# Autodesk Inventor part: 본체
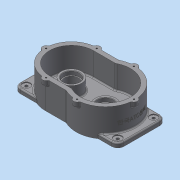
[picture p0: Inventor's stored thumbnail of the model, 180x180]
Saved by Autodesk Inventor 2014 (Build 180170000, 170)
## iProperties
Created: 2025-09
Part Number: 본체
Material: 일반
Document SubType Name: Modeling
Designer: dg
Density: 1 g/cm^3
Appearance: 기본값
Mass: 583.834 g
Surface Area: 1298.21 cm^2
Volume: 583.834 cm^3
Author: dg
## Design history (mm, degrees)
sketch "스케치1"
  geometry: L1 (-118.5, -55)-(118.5, -55); L2 (118.5, -55)-(118.5, 55); L3 (118.5, 55)-(-118.5, 55); L4 (-118.5, 55)-(-118.5, -55); 3 further points
  constraints: 8 end point, 2 midpoint, 2 parallel, 1 horizontal, 1 horizontal alignment, 1 perpendicular, 1 vertical alignment
  dimensions: "d0" = 237 distance of L2.end L3.end; "d1" = 110 distance of L3.end L1.start
extrude "돌출1" new body sketch "스케치1" distance "d2" = 10; taper "d3" = 0 deg
fillet "모깎기1" dims "d4" = 14
hole "구멍1" diameter "d7" = 6.6; stored, may be unused: countersink angle "d11" = 90 deg, drill point angle "d13" = 118 deg; dims "d5" = 10, "d6" = 10, "d8" = 6, "d9" = 18, "d10" = 2, "d12" = 8
hole "구멍2" diameter "d16" = 6.6; stored, may be unused: countersink angle "d20" = 90 deg, drill point angle "d22" = 118 deg; dims "d14" = 10, "d15" = 10, "d17" = 6, "d18" = 18, "d19" = 2, "d21" = 8
hole "구멍3" diameter "d25" = 6.6; stored, may be unused: countersink angle "d29" = 90 deg, drill point angle "d31" = 118 deg; dims "d23" = 10, "d24" = 10, "d26" = 6, "d27" = 18, "d28" = 2, "d30" = 8
hole "구멍4" diameter "d34" = 6.6; stored, may be unused: countersink angle "d38" = 90 deg, drill point angle "d40" = 118 deg; dims "d32" = 10, "d33" = 10, "d35" = 6, "d36" = 18, "d37" = 2, "d39" = 8
sketch "스케치2"
  geometry: L1 (104.5, 55)-(-104.5, 55) reference; L2 (-104.5, -55)-(104.5, -55) reference; L3 (-118.5, 41)-(-118.5, -41) reference; L4 (118.5, -41)-(118.5, 41) reference; L5 (-42.5, 50)-(8.132, 50); L6 (-42.5, -50)-(8.132, -50); L7 (5.684, 60)-(-42.5, 60); L8 (-42.5, -60)-(5.684, -60); A1 r 50 centre (-42.5, 0) between (-42.5, 50) and (-42.5, -50); A2 r 57 centre (35.5, 0) between (8.132, -50) and (8.132, 50); A3 r 60 centre (-42.5, 0) between (-42.5, 60) and (-42.5, -60); A4 r 67 centre (35.5, 0) between (5.684, -60) and (5.684, 60); 1 further point
  constraints: 8 end point, 8 point on circle, 4 centre point, 2 parallel, 2 tangent, 1 horizontal alignment, 1 perpendicular, 1 vertical alignment, 3 other
  dimensions: "d41" = 78 distance of A2.centre A1.centre; "d43" = 50 radius of A1; "d44" = 57 radius of A2; "d45" = 10 distance between parallel lines of L7 L5; "d117" = 76 distance from line of L3 A1.centre
extrude "돌출2" join sketch "스케치2" distance "d46" = 10; taper "d47" = 0 deg
extrude "돌출3" join sketch "스케치2" distance "d48" = 64; taper "d49" = 0 deg
sketch "스케치3"
  geometry: L1 (5.684, 60)-(-42.5, 60) reference; L2 (-42.5, -60)-(5.684, -60) reference; A1 r 57 centre (35.5, 0) between (8.132, -50) and (8.132, 50) reference; A2 r 50 centre (-42.5, 0) between (-42.5, 50) and (-42.5, -50) reference; A3 r 60 centre (-42.5, 0) between (-42.5, 60) and (-42.5, -60) reference; A4 r 67 centre (35.5, 0) between (5.684, -60) and (5.684, 60) reference; A5 r 8 centre (-42.5, 58) between (-34.754, 60) and (-50.361, 59.483); A6 r 8 centre (-100.5, 0) between (-101.983, 7.861) and (-101.983, -7.861); A7 r 8 centre (-42.5, -58) between (-50.361, -59.483) and (-34.754, -60); A8 r 8 centre (35.5, -65) between (27.649, -66.538) and (43.351, -66.538); A9 r 8 centre (35.5, 65) between (43.351, 66.538) and (27.649, 66.538); A10 r 8 centre (100.5, 0) between (102.038, -7.851) and (102.038, 7.851); 7 further points
  constraints: 22 point on circle, 6 centre point, 6 coincident, 5 equal radius, 3 vertical alignment, 2 horizontal alignment, 2 point on line
  dimensions: "d104" = 58 distance of A2.centre point (-100.5, 0); "d105" = 116 distance of point (-42.5, -58) point (-42.5, 58); "d106" = 58 distance of A2.centre point (-42.5, 58); "d107" = 130 distance of point (35.5, -65) point (35.5, 65); "d108" = 65 distance of A1.centre point (35.5, -65); "d109" = 65 horizontal distance of point (100.5, 0) point (35.5, -65); "d119" = 8 radius of A5; "d120" = 78 horizontal distance of point (35.5, 65) point (-42.5, 58)
sketch "스케치6"
  geometry: C1 r 15 at (-35.5, 0) reference; C2 r 17.5 at (-35.5, 0); A1 r 67 centre (-35.5, 0) between (-5.684, 60) and (-73.762, 55) reference; 1 further point
  constraints: 1 centre point, 1 coincident
  dimensions: "d83" = 35 diameter of C2
extrude "돌출12" cut sketch "스케치6" distance "d84" = 8.3; taper "d85" = 0 deg
chamfer "모따기2" distance "d89" = 0.8; stored, may be unused: second distance "d90" = 2, angle "d91" = 30 deg
fillet "모깎기2" dims "d92" = 0.3
fillet "모깎기3" dims "d93" = 3
fillet "모깎기5" dims "d95" = 3
fillet "모깎기6" dims "d96" = 3
fillet "모깎기7" dims "d97" = 13
fillet "모깎기8" dims "d98" = 3
sketch "스케치7"
  geometry: L1 (-7, 0)-(-7, 82) reference; L2 (0, 0)-(0, 82) reference; L3 (-35, 7.5)-(-35, 74.5); L4 (-35, 74.5)-(-25, 74.5); L5 (-25, 74.5)-(-25, 7.5); L6 (-25, 7.5)-(-35, 7.5); 5 further points
  constraints: 3 midpoint, 2 horizontal alignment, 1 horizontal, 1 vertical alignment, 2 other
  dimensions: "d99" = 30 distance from line of L2 point (-30, 41); "d100" = 67 distance of L3.start L3.end; "d101" = 10 distance of L3.end L4.end
feature "엠보싱1" sketch "스케치7" dims "d102" = 0.5, "d103" = 0
hole "구멍6" sketch "스케치3" diameter "d110" = 3.242; stored, may be unused: countersink angle "d114" = 90 deg, drill point angle "d116" = 118 deg; dims "d111" = 8, "d112" = 18, "d113" = 2, "d115" = 10
extrude "돌출13" join sketch "스케치3" distance "d121" = 12; taper "d122" = 0 deg
fillet "모깎기10" dims "d123" = 3
fillet "모깎기11" dims "d124" = 3
node "작업 평면3"
sketch "스케치8"
  geometry: C1 r 16 at (-42.5, 0); C2 r 23.5 at (-42.5, 0); C3 r 18.5 at (-42.5, 0); C4 r 14 at (-42.5, 0); A1 r 50 centre (-42.5, 0) between (-42.5, 50) and (-42.5, -50) reference; 1 further point
  constraints: 4 centre point, 3 coincident, 1 concentric
  dimensions: "d126" = 47 diameter of C2; "d127" = 37 diameter of C3; "d128" = 32 diameter of C1; "d129" = 28 diameter of C4
extrude "돌출14" join sketch "스케치8" stored distance "d130" = 12; taper "d131" = 0 deg
node "작업 평면4"
sketch "스케치9"
  geometry: C1 r 23.5 at (35.5, 0); C2 r 18.5 at (35.5, 0); C3 r 15 at (35.5, 0); A1 r 57 centre (35.5, 0) between (10.654, -51.3) and (10.654, 51.3) reference; 1 further point
  constraints: 3 centre point, 2 coincident, 1 concentric
  dimensions: "d144" = 47 diameter of C1; "d145" = 37 diameter of C2; "d146" = 30 diameter of C3
extrude "돌출18" join sketch "스케치9" stored distance "d147" = 28; taper "d148" = 0 deg
extrude "돌출19" cut sketch "스케치9" distance "d149" = 9; taper "d150" = 0 deg
extrude "돌출20" cut sketch "스케치9" stored distance "d151" = 9; taper "d152" = 0 deg
sketch "스케치10"
  geometry: C1 r 17.962 at (-35.5, 0) reference; C2 r 17.5 at (-35.5, 0); 1 further point
  constraints: 1 centre point, 1 coincident
  dimensions: "d153" = 35 diameter of C2
extrude "돌출21" cut sketch "스케치10" distance "d154" = 8.3; taper "d155" = 0 deg
extrude "돌출22" cut sketch "스케치8" distance "d156" = 9; taper "d157" = 0 deg
extrude "돌출23" cut sketch "스케치8" distance "d158" = 25; taper "d159" = 0 deg
extrude "돌출24" cut sketch "스케치8" distance "d160" = 28; taper "d161" = 0 deg
fillet "모깎기14" dims "d162" = 0.3
fillet "모깎기15" dims "d163" = 0.3
chamfer "모따기4" distance "d164" = 1; stored, may be unused: second distance "d165" = 2, angle "d166" = 30 deg
chamfer "모따기5" distance "d167" = 1; stored, may be unused: second distance "d168" = 2, angle "d169" = 30 deg
fillet "모깎기16" dims "d170" = 3
fillet "모깎기17" dims "d171" = 0.3
node "솔리드1"
other parameters: "d125" = -28, "d143" = -42
